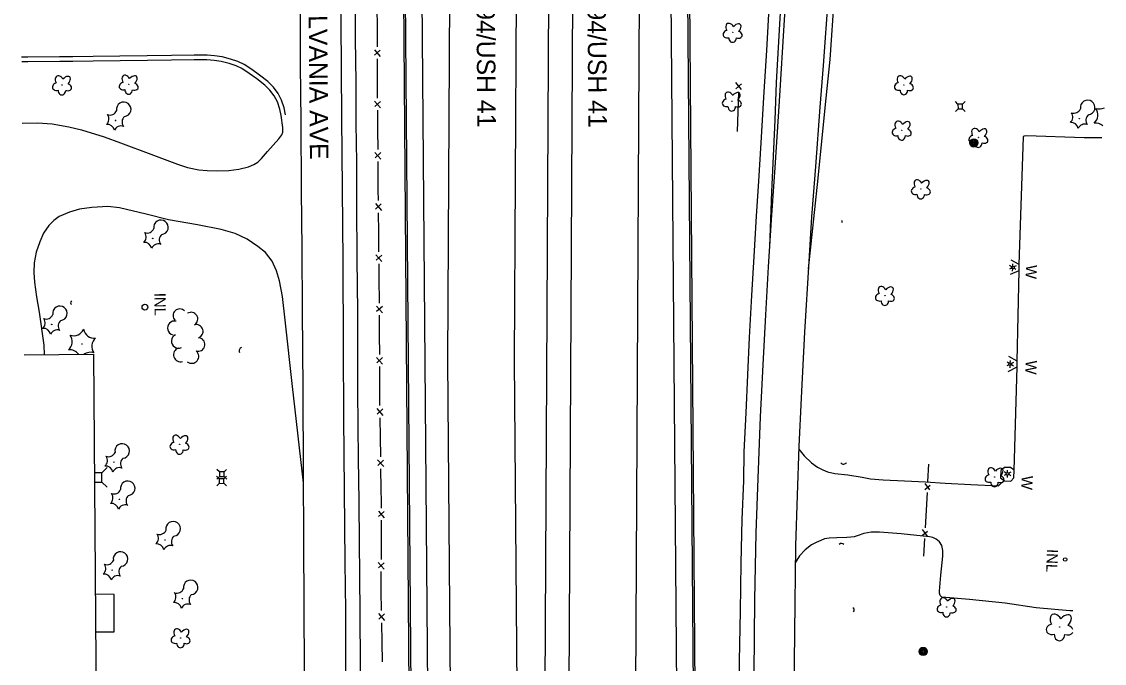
# Model space of a CAD drawing. Extents: x 588843 to 2552415, y 180129 to 269402.
# Drawn here: x 593745 to 594330, y 181719 to 182065 of the extents above; entities that cross this region are included whole.
import ezdxf

# ---------------------------------------------------------------- set-up
doc = ezdxf.new("R2010")
doc.units = 0
for name, color, linetype in [('Default', 7, 'Continuous'), ('E_BLD', 7, 'Continuous'), ('E_DRN', 7, 'Continuous'), ('E_DRN_Text', 7, 'Continuous'), ('E_DWY', 7, 'Continuous'), ('E_FEN_P', 7, 'Continuous'), ('E_LAND_TreeLine_P', 7, 'Continuous'), ('E_LAND_Vegetation', 7, 'Continuous'), ('E_LTG', 7, 'Continuous'), ('E_MISCPROP', 7, 'Continuous'), ('E_PATH_Sidewalk', 7, 'Continuous'), ('E_RDWY', 7, 'Continuous'), ('E_RDWY_Gravel', 7, 'Continuous'), ('E_RDWY_Text', 7, 'Continuous'), ('E_UTL_AG_Bold', 7, 'Continuous'), ('E_WAL', 7, 'Continuous'), ('E_WAL_Text', 7, 'Continuous'), ('P_BMGRD', 7, 'Continuous'), ('P_RDWY_LaneEdge', 7, 'Continuous'), ('P_RDWY_PavtEdge', 7, 'Continuous'), ('P_RDWY_ShldPaved', 7, 'Continuous'), ('P_TC_BarrierConc', 7, 'Continuous')]:
    doc.layers.add(name, color=color, linetype=linetype)

# ---------------------------------------------------------------- blocks, each defined once
blk = doc.blocks.new('CULV2')
at = {"layer": 'E_DRN'}
blk.add_arc((19.7, 14.8), 24.6, 216.8699, 323.1301, dxfattribs=at)
blk = doc.blocks.new('POLE')
at = {"layer": 'Default'}
for radius in [4.46, 3.35, 2.23, 1.12]:
    blk.add_circle((0, 0), radius, dxfattribs=at)
blk = doc.blocks.new('DTRE')
at = {"layer": 'Default'}
blk.add_circle((-0.2, 0), 0.183, dxfattribs=at)
for centre, major_axis, ratio in [((-5.9, 0.2), (4.93, -0.12), 0.832022), ((-1.9, 5.3), (1.36, -4.98), 0.782863), ((4.1, 2.7), (-5.27, -2.93), 0.691916), ((-2.5, -5.2), (1.8, 4.86), 0.716896), ((3.5, -3.7), (-5.01, 4.58), 0.560249)]:
    blk.add_ellipse(centre, major_axis=major_axis, ratio=ratio, start_param=1.570796, end_param=4.712389, dxfattribs=at)
blk = doc.blocks.new('W_1')
at = {"layer": 'E_WAL_Text'}
blk.add_text('W', height=12, dxfattribs=at).set_placement((-4.5, -6))
blk = doc.blocks.new('PED')
at = {"layer": 'Default'}
for p, q in [((-2.5, 2.5), (-5.3, 5.3)), ((2.5, 2.5), (5.3, 5.3)), ((-2.5, -2.5), (-5.3, -5.3)), ((2.5, -2.5), (5.3, -5.3))]:
    blk.add_line(p, q, dxfattribs=at)
blk.add_lwpolyline([(-2.5, -2.5), (2.5, -2.5), (2.5, 2.5), (-2.5, 2.5)], close=True, dxfattribs=at)
blk = doc.blocks.new('INLT_9')
at = {"layer": 'E_DRN_Text'}
blk.add_text('INL', height=12, dxfattribs=at).set_placement((-11, -6))
blk = doc.blocks.new('LPOL')
at = {"layer": 'Default'}
for p, q in [((-4, 0), (-1.5, 0)), ((-0.7, 1.3), (-2, 3.5)), ((0.7, 1.3), (2, 3.5)), ((1.5, 0), (4, 0)), ((-2, -3.5), (-0.7, -1.3)), ((2, -3.5), (0.7, -1.3))]:
    blk.add_line(p, q, dxfattribs=at)
for radius in [1.5, 1.5, 1.5, 0.125]:
    blk.add_circle((0, 0), radius, dxfattribs=at)
blk = doc.blocks.new('CTRE')
at = {"layer": 'Default'}
blk.add_circle((0, 0), 0.223, dxfattribs=at)
for centre, start, end in [((-12, 9), 280.2067, 5.9716), ((-13.8, -5.9), 340.2113, 65.9762), ((1.8, 14.9), 220.2113, 305.9762), ((13.8, 5.9), 160.2113, 245.9762), ((-1.8, -14.9), 40.2113, 125.9762), ((12, -9), 185.9272, 100.2511)]:
    blk.add_arc(centre, 7.87, start, end, dxfattribs=at)
blk = doc.blocks.new('INLT_10')
at = {"layer": 'E_DRN_Text'}
blk.add_text('INL', height=12, dxfattribs=at).set_placement((-11, -6))
blk = doc.blocks.new('U203')
at = {"layer": 'E_UTL_AG_Bold'}
for p, q in [((2.48, 2.52), (5.29, 5.37)), ((2.52, -2.48), (5.37, -5.29))]:
    blk.add_line(p, q, dxfattribs=at)
blk.add_lwpolyline([(-1.54, -2.51), (2.52, -2.48), (2.48, 2.52), (-1.58, 2.49)], dxfattribs=at)
blk = doc.blocks.new('U204')
at = {"layer": 'E_LAND_Vegetation'}
blk.add_circle((-0.02, 0), 0.167, dxfattribs=at)
for centre, radius, start, end in [((-4.51, 10.35), 5.9, 250.61087, 336.37578), ((6.7, 9.07), 5.91, 190.65065, 276.32675), ((-11.22, 1.28), 5.9, 310.61086, 36.37577), ((11.19, -1.27), 5.9, 130.61087, 216.37578), ((-6.68, -9.02), 5.9, 35.76984, 96.37116), ((4.48, -10.34), 5.9, 70.61086, 125.77361)]:
    blk.add_arc(centre, radius, start, end, dxfattribs=at)

msp = doc.modelspace()

# ---------------------------------------------------------------- linework, layer by layer
at = {"layer": 'E_BLD'}
msp.add_lwpolyline([(593746.54, 181885.28), (593783.92, 181885.57), (593785.4, 181695.78), (593781.62, 181695.75), (593781.67, 181689.27), (593769.25, 181689.17), (593769.32, 181680.04), (593748.22, 181678.18)], dxfattribs=at)
at = {"layer": 'E_DRN'}
for centre, radius in [((593811.76, 181910.98), 1.56), ((594308.89, 181774.66), 0.955)]:
    msp.add_circle(centre, radius, dxfattribs=at)
at = {"layer": 'E_DWY'}
for points in [[(593887.76, 182014.94), (593887.01, 182018.56), (593885.63, 182022.8), (593883.7, 182026.45), (593881.21, 182029.83), (593878.13, 182032.77), (593873.68, 182036.33), (593869.56, 182039.32), (593865.31, 182042.01), (593861.97, 182043.59), (593858, 182044.98), (593853.44, 182046.15), (593849.4, 182046.75), (593845.31, 182047.05), (593838.28, 182047.05), (593826.12, 182046.91), (593813.02, 182046.78), (593798.29, 182046.54), (593783.76, 182046.41), (593772.86, 182046.23), (593765.68, 182046.19), (593748.44, 182046), (593745.16, 182045.96)], [(593885.31, 182014.43), (593884.59, 182017.91), (593883.32, 182021.83), (593881.57, 182025.12), (593879.32, 182028.18), (593876.48, 182030.88), (593872.16, 182034.34), (593868.15, 182037.25), (593864.1, 182039.81), (593861.02, 182041.27), (593857.28, 182042.58), (593852.95, 182043.7), (593849.12, 182044.26), (593845.21, 182044.55), (593838.3, 182044.55), (593826.15, 182044.41), (593813.06, 182044.28), (593798.33, 182044.04), (593783.79, 182043.91), (593772.89, 182043.73), (593765.7, 182043.69), (593748.47, 182043.5), (593745.18, 182043.46)], [(593745.47, 182010.43), (593753.64, 182010.52), (593761.73, 182010.03), (593770.58, 182008.41), (593777.55, 182006.67), (593789.81, 182003.05), (593798.48, 181999.7), (593814.95, 181993.55), (593829.41, 181988.14), (593834.67, 181986.41), (593840.9, 181985.19), (593845.47, 181984.71), (593851.02, 181984.58), (593857.02, 181984.76), (593862.5, 181985.57), (593867.74, 181986.84), (593870.6, 181987.94), (593872.84, 181989.36), (593874.7, 181991.2), (593877.96, 181995.13), (593884.07, 182001.87), (593885.72, 182004.09), (593886.18, 182005.41), (593886.25, 182006.56), (593886.26, 182008.06), (593885.31, 182014.43)], [(594284.13, 181934.05), (594286.45, 182002.94), (594286.63, 182003.46), (594287.02, 182003.6), (594287.99, 182003.73), (594319.18, 182002.68), (594328.65, 182002.63)], [(593897.4, 181816.03), (593891.47, 181868.18), (593887.58, 181903.93), (593886.12, 181916.74), (593884.52, 181925.23), (593882.86, 181930.55), (593880.42, 181935.76), (593876.85, 181940.58), (593872.84, 181943.75), (593866.94, 181947.67), (593860.59, 181950.73), (593852.86, 181952.98), (593840.24, 181955.42), (593824.55, 181958.17), (593812.37, 181961.26), (593797.94, 181964.66), (593791.8, 181965.3), (593783.01, 181964.86), (593776.48, 181963.86), (593771.06, 181962.33), (593765.38, 181959.89), (593762.52, 181957.87), (593759.78, 181955.03), (593757.04, 181950.93), (593754.94, 181946.31), (593752.92, 181940.74), (593751.98, 181934.91), (593751.66, 181929.72), (593752.02, 181924.52), (593753.24, 181916.52), (593754.62, 181908.29), (593757.13, 181890.37), (593757.29, 181885.36)], [(594283.04, 181881.8), (594284.08, 181930.81)], [(594281.36, 181822.73), (594283.06, 181878.7)], [(594165.05, 181834.23), (594167.92, 181830.69), (594171.91, 181826.87), (594175.15, 181824.59), (594178, 181823.11), (594180.54, 181822.12), (594184.48, 181821.16), (594191.59, 181820.36), (594199.19, 181819.24), (594203.69, 181818.31), (594210.56, 181817.75), (594222.14, 181817.21), (594233.44, 181816.67), (594244.07, 181815.99), (594257.88, 181815.12), (594272.99, 181814.49)], [(594272.99, 181814.49), (594276, 181817.3)], [(594313.11, 181746.93), (594311.52, 181746.97), (594293.28, 181748.66), (594276.55, 181751.05), (594257.2, 181753.03), (594242.31, 181754.35), (594241.41, 181755.33), (594240.99, 181756.42), (594240.97, 181757.6), (594241.74, 181766.18), (594242.8, 181776.47), (594242.75, 181779.64), (594242.24, 181782.3), (594241.09, 181784.19), (594239.29, 181785.59), (594237.44, 181786.51), (594235.7, 181786.86), (594220.32, 181788.51), (594208.64, 181789.44), (594204.04, 181789.53), (594200.2, 181788.81), (594197.12, 181787.64), (594194.88, 181786.92), (594193.1, 181786.69), (594190.98, 181786.52), (594185.6, 181786.48), (594181.45, 181786.25), (594178.97, 181785.78), (594176.91, 181785.02), (594174.36, 181783.92), (594171.91, 181782.67), (594168.37, 181779.9), (594165.39, 181776.7), (594163.11, 181772.95)]]:
    msp.add_lwpolyline(points, dxfattribs=at)
at = {"layer": 'E_FEN_P'}
for p, q in [((593935.71, 182049.96), (593938.92, 182046.29)), ((593938.91, 182049.8), (593935.78, 182047.02)), ((594130.92, 182028.89), (594134.15, 182031.55)), ((594134.12, 182028.61), (594131.03, 182032.4)), ((593935.84, 182022.27), (593939.08, 182018.61)), ((593939.05, 182022.12), (593935.93, 182019.33)), ((593936.03, 181994.59), (593939.26, 181990.93)), ((593939.24, 181994.44), (593936.12, 181991.65)), ((593936.25, 181966.9), (593939.5, 181963.25)), ((593939.46, 181966.76), (593936.35, 181963.96)), ((593936.55, 181939.22), (593939.79, 181935.57)), ((593939.76, 181939.08), (593936.65, 181936.28)), ((593936.82, 181911.54), (593940.04, 181907.88)), ((593940.02, 181911.39), (593936.9, 181908.6)), ((593936.95, 181883.86), (593940.17, 181880.19)), ((593940.15, 181883.71), (593937.03, 181880.92)), ((593937.07, 181856.18), (593940.3, 181852.51)), ((593940.28, 181856.02), (593937.15, 181853.24)), ((593937.49, 181828.48), (593940.76, 181824.85)), ((593940.7, 181828.36), (593937.61, 181825.54)), ((594233.02, 181812.56), (594235.98, 181814.89)), ((594235.89, 181812.24), (594233.2, 181815.71)), ((593937.86, 181800.83), (593941.06, 181797.14)), ((593941.06, 181800.65), (593937.92, 181797.89)), ((594234.48, 181787.36), (594231.79, 181790.83)), ((594231.61, 181787.67), (594234.57, 181790)), ((593937.81, 181773.14), (593941.01, 181769.46)), ((593941.02, 181772.97), (593937.87, 181770.2)), ((593937.97, 181745.44), (593941.23, 181741.81)), ((593941.18, 181745.32), (593938.08, 181742.51))]:
    msp.add_line(p, q, dxfattribs=at)
for points in [[(593937.12, 182072.73), (593937.15, 182062.16)], [(593937.15, 182062.16), (593937.18, 182051.59)], [(593937.2, 182045.05), (593937.22, 182037.39), (593937.24, 182034.48)], [(593937.24, 182034.48), (593937.31, 182023.91)], [(594132.24, 182016.47), (594132.59, 182027.04)], [(593937.36, 182017.36), (593937.43, 182006.79)], [(594131.9, 182005.91), (594132.24, 182016.47)], [(593937.43, 182006.79), (593937.5, 181996.22)], [(593937.55, 181989.68), (593937.62, 181979.11)], [(593937.62, 181979.11), (593937.65, 181974.39), (593937.71, 181968.54)], [(593937.78, 181962), (593937.9, 181951.43)], [(593937.9, 181951.43), (593938.01, 181940.86)], [(593938.08, 181934.32), (593938.19, 181923.75)], [(593938.19, 181923.75), (593938.28, 181916.13), (593938.29, 181913.18)], [(593938.32, 181906.63), (593938.37, 181896.06)], [(593938.37, 181896.06), (593938.42, 181885.49)], [(593938.45, 181878.95), (593938.5, 181868.38)], [(593938.5, 181868.38), (593938.55, 181857.81)], [(593938.61, 181851.27), (593938.78, 181840.7)], [(593938.78, 181840.7), (593938.95, 181830.13)], [(594234.81, 181816.74), (594235.35, 181826.24)], [(593939.05, 181823.59), (593939.23, 181813.02)], [(593939.23, 181813.02), (593939.35, 181805.54), (593939.34, 181802.45)], [(594233.94, 181801.35), (594234.48, 181810.85)], [(594233.4, 181791.85), (594233.94, 181801.35)], [(593939.33, 181795.91), (593939.31, 181785.34)], [(593939.31, 181785.34), (593939.3, 181774.77)], [(594232.53, 181776.47), (594233.07, 181785.97)], [(593939.29, 181768.22), (593939.27, 181757.65)], [(593939.27, 181757.65), (593939.42, 181747.09)], [(593939.52, 181740.55), (593939.68, 181729.99)], [(593939.68, 181729.99), (593939.84, 181719.43)]]:
    msp.add_lwpolyline(points, dxfattribs=at)
at = {"layer": 'E_LAND_TreeLine_P'}
for centre, radius, start, end in [((593830.57, 181906.39), 3.64, 43.86807, 223.86807), ((593836.68, 181904.57), 3.64, 301.80535, 121.80535), ((593827.75, 181899.69), 3.78, 75.43284, 255.43284), ((593839.55, 181897.91), 3.64, 287.07719, 107.07719), ((593829.82, 181892.61), 3.78, 115.22071, 295.22071), ((593840.5, 181890.82), 3.64, 253.44862, 73.44862), ((593830.96, 181885.28), 3.78, 107.33574, 287.33574), ((593837.04, 181884.43), 3.78, 230.21549, 50.21549)]:
    msp.add_arc(centre, radius, start, end, dxfattribs=at)
at = {"layer": 'E_LAND_Vegetation'}
msp.add_circle((594305.97, 181738.26), 0.128, dxfattribs=at)
for centre, start, end in [((594327.46, 182023.92), 250.61087, 296.49988), ((594320.75, 182014.85), 310.61086, 36.37577), ((594325.29, 182004.55), 47.94477, 96.37116)]:
    msp.add_arc(centre, 5.9, start, end, dxfattribs=at)
for centre, major_axis, ratio, start_param, end_param in [((594304.05, 181741.22), (2.06, -3.69), 0.691916, 1.570796, 4.712389), ((594308.56, 181740.87), (-3.2, -3.51), 0.560249, 1.570796, 4.712389), ((594302.25, 181737.07), (3.49, 0.96), 0.782863, 1.570796, 4.712389), ((594309.65, 181736.65), (-3.4, 1.26), 0.716896, 3.705973, 4.712389), ((594305.87, 181734.28), (0.08, 3.45), 0.832022, 1.570796, 4.712389), ((594309.65, 181736.65), (-3.4, 1.26), 0.716896, 1.570796, 3.078703)]:
    msp.add_ellipse(centre, major_axis=major_axis, ratio=ratio, start_param=start_param, end_param=end_param, dxfattribs=at)
at = {"layer": 'E_PATH_Sidewalk'}
msp.add_lwpolyline([(593785.09, 181735.58), (593795.14, 181735.64), (593795.16, 181755.84), (593784.93, 181755.89)], dxfattribs=at)
at = {"layer": 'E_RDWY'}
for points in [[(593897.83, 181748.36), (593897.58, 181786.05), (593897.37, 181821.04), (593897.17, 181866.88), (593896.89, 181909.03), (593896.66, 181942.48), (593896.43, 181973.88), (593896.2, 182011.63), (593895.82, 182041.7), (593895.77, 182075.15), (593895.43, 182106.27), (593894.88, 182136.31), (593894.66, 182169.49), (593894.34, 182197.68), (593894.04, 182236.82), (593893.6, 182274.85), (593893.15, 182305.55), (593892.83, 182339.74)], [(593915.11, 182338.51), (593915.48, 182293.95), (593916.04, 182242.35), (593916.42, 182198.12), (593916.78, 182150.01), (593917.13, 182107.48), (593917.55, 182065.48), (593917.93, 182013.22), (593918.23, 181974.95), (593918.67, 181935.77), (593918.94, 181889.51), (593919.07, 181851.42), (593919.47, 181812.1), (593919.77, 181773.06), (593920.04, 181747.12)], [(594141.19, 181752.86), (594142.03, 181789.12), (594143.04, 181818.45), (594144.39, 181851.83), (594145.71, 181879.87), (594147.17, 181906.86), (594148.72, 181932.84), (594150.31, 181958.23), (594152.3, 181986.45), (594154.63, 182022.26), (594157.29, 182066.17), (594159.21, 182096.19), (594161.47, 182130.13), (594164.37, 182167.96), (594167.84, 182199.73), (594172.28, 182230.72), (594177.09, 182258.36), (594184.16, 182291.53), (594190.95, 182319.38)], [(594213.92, 182315.25), (594207.27, 182288.07), (594200.84, 182257.62), (594195.18, 182226.14), (594191.67, 182201.15), (594188.79, 182175.31), (594185.77, 182142.25), (594183.32, 182111.32), (594180.97, 182079.14), (594178.24, 182041.44), (594176.39, 182019.02), (594173.96, 181986.9), (594171.95, 181959.7), (594170.37, 181935.57), (594168.02, 181897.41), (594166.24, 181862.01), (594165.11, 181835.75), (594164.11, 181809.42), (594163.24, 181782.07), (594162.81, 181751.04)], [(594142.93, 181166.54), (594142.29, 181215.68), (594142.07, 181268.19), (594142.07, 181313.28), (594142.01, 181359.34), (594141.95, 181402.92), (594141.64, 181442.84), (594141.47, 181479.37), (594141.56, 181516.12), (594141.22, 181558.09), (594141.09, 181594.3), (594140.95, 181642.35), (594140.72, 181693.25), (594141.19, 181752.86)], [(594162.81, 181751.04), (594162.53, 181719.29), (594162.57, 181679.47), (594162.77, 181638.36), (594162.86, 181590.21), (594163.17, 181543.56), (594163.69, 181487.44), (594163.82, 181444.77), (594163.88, 181400.76), (594163.9, 181350.35), (594163.93, 181308.87), (594164.11, 181250.65), (594164.38, 181188.88), (594164.29, 181166.89)], [(593898.68, 181640.91), (593898.23, 181683.47), (593897.83, 181748.36)], [(593920.04, 181747.12), (593920.2, 181707.24), (593920.49, 181659.97), (593920.92, 181589.62), (593921.33, 181527.56), (593921.83, 181466.82), (593922.3, 181401.73), (593922.65, 181362.99), (593923.47, 181293.57), (593923.63, 181239.18), (593923.73, 181174.95)]]:
    msp.add_lwpolyline(points, dxfattribs=at)
at = {"layer": 'E_RDWY_Gravel'}
for points in [[(594149.4, 181943.66), (594150.46, 181973.34), (594152.21, 182012.02), (594153.04, 182032.35), (594154.8, 182063.74), (594156.43, 182091.6), (594158.44, 182124.98), (594160.44, 182154.52), (594162.24, 182173.66), (594165.33, 182200.19), (594169.02, 182227.87), (594172.9, 182250.6), (594177.45, 182274.37), (594182.55, 182297.4), (594188.24, 182319.98)], [(594217.09, 182313.98), (594211.58, 182292.52), (594205.52, 182266.28), (594199.84, 182237.42), (594195.66, 182210.86), (594192.58, 182186.18), (594191.15, 182172.33), (594188.46, 182142.83), (594186.29, 182111.73), (594184.21, 182079.12), (594181.78, 182044.74), (594179.11, 182018.55), (594175.22, 181980.58), (594170.12, 181931.6)]]:
    msp.add_lwpolyline(points, dxfattribs=at)
at = {"layer": 'E_WAL'}
for points in [[(594279.47, 181928.77), (594284.08, 181930.81), (594284.13, 181934.05), (594279.71, 181936.41)], [(594278.2, 181876.21), (594283.06, 181878.7), (594283.04, 181881.8), (594278.42, 181884.26)], [(594274.14, 181822.71), (594273.98, 181818.81), (594276.14, 181817.19), (594279.49, 181817), (594281.24, 181818.77), (594281.36, 181822.85)], [(594281.36, 181822.85), (594279.38, 181824.36), (594276.21, 181824.38), (594274.14, 181822.71)]]:
    msp.add_lwpolyline(points, dxfattribs=at)
at = {"layer": 'P_BMGRD'}
for points in [[(593924.49, 182168.19), (593924.92, 182116.95), (593925.15, 182096.06), (593925.3, 182076.65), (593925.33, 182055.84), (593925.66, 182032.43), (593925.76, 182010.23), (593926, 181989.36), (593926.06, 181966.51), (593926.28, 181936.83), (593926.52, 181908.62), (593926.6, 181885.67), (593926.57, 181866.09), (593926.83, 181846.68), (593927.02, 181829.11), (593927.24, 181806.22), (593927.54, 181783.38), (593927.74, 181767.11), (593927.92, 181744.23), (593928.11, 181719.16), (593928.07, 181699.72)], [(594132.8, 181694.12), (594132.98, 181719.98), (594133.45, 181746.83), (594133.82, 181772.64), (594134.46, 181796.36), (594135.31, 181817.17), (594135.49, 181832.82), (594136.5, 181853.92), (594137.52, 181874.51), (594138.38, 181894.67), (594139.57, 181917.35), (594140.91, 181938.43), (594142.25, 181960.09), (594143.4, 181979.01), (594144.6, 181999.82), (594146.31, 182027.2), (594147.79, 182049.63), (594149.26, 182075.86), (594150.69, 182098.83), (594155.14, 182160.77)]]:
    msp.add_lwpolyline(points, dxfattribs=at)
at = {"layer": 'P_RDWY_LaneEdge'}
for p, q in [((593975.42, 181882.13), (593976.9, 182168.61)), ((594011.42, 181882.41), (594012.9, 182168.89)), ((594040.13, 181538.87), (594043.4, 182169.14)), ((594076.13, 181539.16), (594079.4, 182169.42)), ((593978.69, 181468.6), (593975.42, 181882.13)), ((594014.69, 181468.89), (594011.42, 181882.41))]:
    msp.add_line(p, q, dxfattribs=at)
at = {"layer": 'P_RDWY_PavtEdge'}
for p, q in [((593966.44, 181468.5), (593960.9, 182168.48)), ((594100.93, 181469.57), (594095.4, 182169.55))]:
    msp.add_line(p, q, dxfattribs=at)
at = {"layer": 'P_RDWY_ShldPaved'}
for p, q in [((593956.44, 181468.43), (593950.9, 182168.4)), ((594110.93, 181469.65), (594105.4, 182169.63))]:
    msp.add_line(p, q, dxfattribs=at)
at = {"layer": 'P_TC_BarrierConc'}
for p, q in [((593957.44, 181468.43), (593951.9, 182168.41)), ((594027.13, 181538.94), (594030.4, 182169.2)), ((594109.93, 181469.64), (594104.4, 182169.62))]:
    msp.add_line(p, q, dxfattribs=at)

# ---------------------------------------------------------------- block references
at = {"layer": 'E_DRN'}
for p, xscale, yscale, rotation in [((594188.5, 181957.76), 0.024878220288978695, 0.02487822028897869, -94.3624537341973), ((593772.1, 181914.35), 0.05144359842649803, 0.05144359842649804, -87.98622683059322), ((593864.01, 181889.14), 0.07217361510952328, 0.07217361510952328, -114.95370011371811), ((594187.73, 181826.87), 0.07831160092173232, 0.07831160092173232, 4.91759199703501), ((594189.4, 181782.74), 0.06383460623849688, 0.06383460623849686, 178.13202280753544), ((594194.65, 181746.5), 0.05307847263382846, 0.05307847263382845, 101.48324745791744)]:
    msp.add_blockref('CULV2', p, dxfattribs=dict(at, xscale=xscale, yscale=yscale, rotation=rotation))
at = {"layer": 'E_DRN_Text'}
for name, p, xscale, yscale, rotation in [('INLT_10', (593819.92, 181913.24), 0.5000000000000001, 0.5000000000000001, -89.60045983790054), ('INLT_9', (594301.89, 181774.81), 0.5, 0.4999999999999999, -91.92914160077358)]:
    msp.add_blockref(name, p, dxfattribs=dict(at, xscale=xscale, yscale=yscale, rotation=rotation))
at = {"layer": 'E_LAND_Vegetation', "xscale": 0.5000000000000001}
for name, p, yscale, rotation in [('DTRE', (594129.31, 182059.43), 0.5000000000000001, 90.39954016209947), ('DTRE', (593766.99, 182031.06), 0.5000000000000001, 90.39954016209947), ('DTRE', (593803.06, 182031.37), 0.5000000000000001, 90.39954016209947), ('DTRE', (594221.83, 182031.15), 0.5000000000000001, 90.39954016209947), ('DTRE', (594128.85, 182022.32), 0.5000000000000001, 90.39954016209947), ('CTRE', (593795.85, 182011.8), 0.5000000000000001, 90.39954016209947), ('CTRE', (594316.61, 182012.81), 0.5000000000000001, 90.39954016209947), ('DTRE', (594220.66, 182006.6), 0.5000000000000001, 90.39954016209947), ('DTRE', (594262.09, 182002.7), 0.5000000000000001, 90.39954016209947), ('DTRE', (594230.97, 181974.87), 0.5000000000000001, 90.39954016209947), ('CTRE', (593815.98, 181948.08), 0.5000000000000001, 90.39954016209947), ('DTRE', (594211.58, 181917.33), 0.5000000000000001, 90.39954016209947), ('CTRE', (593761.4, 181901.63), 0.5000000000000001, 90.39954016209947), ('CTRE', (593795.02, 181827.25), 0.5000000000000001, 90.39954016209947), ('DTRE', (593830.48, 181836.95), 0.5000000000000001, 90.39954016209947), ('DTRE', (594270.83, 181819.4), 0.5000000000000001, 90.39954016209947), ('CTRE', (593798.01, 181807.12), 0.5000000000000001, 90.39954016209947), ('CTRE', (593822.55, 181785.22), 0.5000000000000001, 90.39954016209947), ('CTRE', (593794.14, 181768.93), 0.5000000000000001, 90.39954016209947), ('CTRE', (593832.04, 181753.6), 0.5000000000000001, 90.39954016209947), ('DTRE', (594244.94, 181749.11), 0.5, 90.08344940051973), ('DTRE', (593831.04, 181732.42), 0.5, 90.08344940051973)]:
    msp.add_blockref(name, p, dxfattribs=dict(at, yscale=yscale, rotation=rotation))
at = {"layer": 'E_LAND_Vegetation'}
msp.add_blockref('U204', (593777.77, 181891.08), dxfattribs=at)
at = {"layer": 'E_LTG', "xscale": 0.5, "yscale": 0.4999999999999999, "rotation": 88.07085839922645}
for p in [(594280.61, 181932.39), (594279.24, 181880.2), (594277.77, 181820.98)]:
    msp.add_blockref('LPOL', p, dxfattribs=at)
at = {"layer": 'E_MISCPROP'}
for p, xscale, yscale, rotation in [((594259.58, 181999.68), 0.5, 0.4999999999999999, 88.07085839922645), ((594232.21, 181725.02), 0.5000000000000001, 0.5, 90.08344940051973)]:
    msp.add_blockref('POLE', p, dxfattribs=dict(at, xscale=xscale, yscale=yscale, rotation=rotation))
at = {"layer": 'E_UTL_AG_Bold', "xscale": 0.4999999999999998, "yscale": 0.49999999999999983, "rotation": 90.4534712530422}
for p in [(594252.27, 182019.37), (593853.18, 181817.08), (593853.27, 181820.71)]:
    msp.add_blockref('PED', p, dxfattribs=at)
at = {"layer": 'E_UTL_AG_Bold'}
msp.add_blockref('U203', (593786, 181819.01), dxfattribs=at)
at = {"layer": 'E_WAL_Text', "xscale": 0.5, "yscale": 0.5000000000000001, "rotation": -92.94348037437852}
for p in [(594290.69, 181931.56), (594290.6, 181879.98), (594288.39, 181817.68)]:
    msp.add_blockref('W_1', p, dxfattribs=at)

# ---------------------------------------------------------------- texts
at = {"layer": 'E_RDWY_Text'}
for s, p in [('IH 94/USH 41', (593990.66, 182090.55)), ('IH 94/USH 41', (594050.67, 182090.39)), ('SYLVANIA AVE', (593900.05, 182086.49))]:
    msp.add_text(s, height=10, rotation=270.51272, dxfattribs=at).set_placement(p)

doc.saveas('drawing.dxf')
